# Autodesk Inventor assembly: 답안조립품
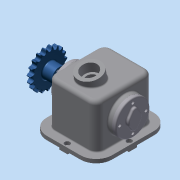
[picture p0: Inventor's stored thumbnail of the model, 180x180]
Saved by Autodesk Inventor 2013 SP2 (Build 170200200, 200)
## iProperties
Created: 2014-11
Part Number: 답안조립품
Document SubType Name: Assembly
Designer: dgall
Author: dgall
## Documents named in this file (9)
- C:\Documents and Settings\dgall\바탕 화면\441122v1006\답안조립품.iam
- C:\Documents and Settings\dgall\바탕 화면\441122v1006\1.본체.ipt
- C:\Documents and Settings\dgall\바탕 화면\441122v1006\뒤커버.ipt
- C:\Documents and Settings\dgall\바탕 화면\441122v1006\앞커버.ipt
- C:\Documents and Settings\dgall\바탕 화면\441122v1006\오일실.ipt
- C:\Documents and Settings\dgall\바탕 화면\441122v1006\베어링 6205.ipt
- C:\Documents and Settings\dgall\바탕 화면\441122v1006\편심축.ipt
- C:\Documents and Settings\dgall\바탕 화면\441122v1006\키 8x8.ipt
- C:\Documents and Settings\dgall\바탕 화면\441122v1006\5-체인 스프로킷.ipt
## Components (2 placed, 2 different names)
1. 1.본체:1
2. 5-체인 스프로킷:1
